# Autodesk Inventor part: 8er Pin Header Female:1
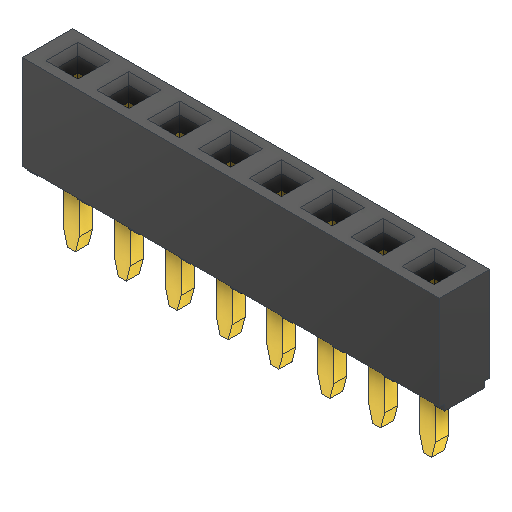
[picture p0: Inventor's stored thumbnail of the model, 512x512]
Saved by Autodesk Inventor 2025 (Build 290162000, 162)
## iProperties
Created: 2025-05
Part Number: 8er Pin Header Female:1
Material: Generico
Document SubType Name: Modeling
Designer: R5800u
Density: 1 g/cm^3
Appearance: Default
Author: R5800u
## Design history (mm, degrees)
feature "Base1"
node "Solido1"
